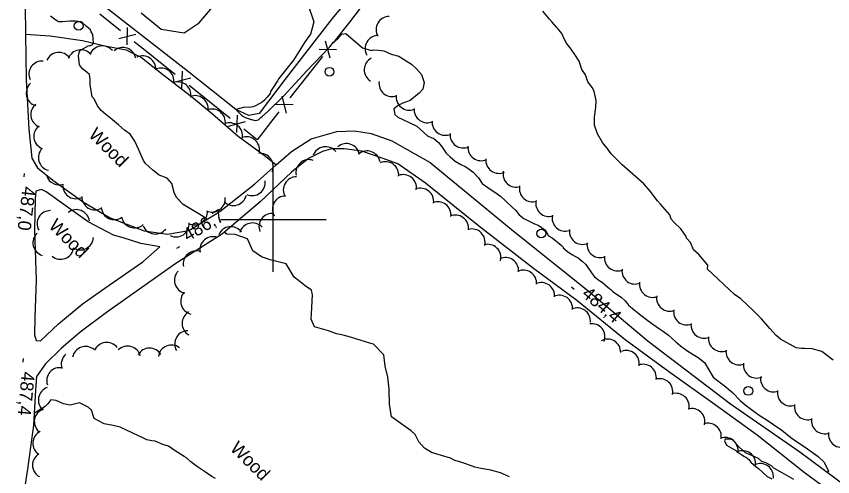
# Model space of a CAD drawing. Extents: x 642515 to 647219, y 6080136 to 6084356.
# Drawn here: x 642941.6 to 643127.5, y 6082341.5 to 6082446.4 of the extents above; entities that cross this region are included whole.
import ezdxf

# ---------------------------------------------------------------- set-up
doc = ezdxf.new("R2010")
doc.units = 0
for name, color, linetype in [('Level 19', 7, 'Continuous'), ('Level 2', 7, 'Continuous'), ('Level 21', 7, 'Continuous'), ('Level 22', 7, 'Continuous'), ('Level 3', 7, 'Continuous'), ('Level 36', 7, 'Continuous'), ('Level 37', 7, 'Continuous'), ('Level 4', 7, 'Continuous'), ('Level 44', 7, 'Continuous'), ('Level 61', 7, 'Continuous')]:
    doc.layers.add(name, color=color, linetype=linetype)

msp = doc.modelspace()

# ---------------------------------------------------------------- linework, layer by layer
at = {"layer": 'Level 19'}
msp.add_lwpolyline([(642969.97, 6082447.17), (642974.56, 6082443.51), (642979.82, 6082442.61), (642983.18, 6082444.95), (642987.04, 6082449.51)], dxfattribs=at)
at = {"layer": 'Level 2'}
for points in [[(643008.19, 6082448.5), (643009.06, 6082445.82), (643009.33, 6082445.11), (643008.96, 6082443.68), (643008.58, 6082442.34), (643007.37, 6082440.67), (643004.71, 6082436.4), (643001.36, 6082432.22), (643001.02, 6082431.68), (642999.93, 6082429.98), (642999.44, 6082429.27), (642999.34, 6082428.82), (642998.7, 6082427.95), (642998.12, 6082427.32), (642997.54, 6082426.85), (642996.2, 6082426.06), (642995.53, 6082425.74), (642994.6, 6082425.65)], [(643115.6, 6082372.84), (643114.66, 6082373.68), (643113.21, 6082375.29), (643111.32, 6082377.44), (643109.53, 6082379.2), (643106.56, 6082382.02), (643105.13, 6082383), (643099.01, 6082388.79), (643099.05, 6082389.68), (643096.98, 6082392.15), (643095.79, 6082393.21), (643095.14, 6082394.87), (643094.2, 6082395.86), (643094.1, 6082396.26), (643092.88, 6082397.97), (643091.43, 6082399.42), (643090.75, 6082400.19), (643090.38, 6082401.13), (643088.31, 6082403.6), (643087.62, 6082404.37), (643085.9, 6082406.53), (643084.51, 6082408.23), (643079.52, 6082412.56), (643078.24, 6082413.86), (643077.04, 6082415.09), (643076.35, 6082416.02), (643075.05, 6082417.64), (643073.9, 6082419.6), (643073.23, 6082421.57), (643073.22, 6082423.42), (643073.52, 6082425.61), (643073.6, 6082427.22), (643073.29, 6082428.57), (643073.18, 6082429.29), (643072.81, 6082430.07), (643071.77, 6082431.47), (643071.49, 6082432.18), (643071.21, 6082433.05), (643070.33, 6082434.29), (643069.75, 6082436.19), (643068.79, 6082437.67), (643067.91, 6082438.92), (643066.87, 6082440.31), (643066.34, 6082441.25), (643065.79, 6082442.51), (643064.84, 6082443.67), (643064.58, 6082443.9), (643063.64, 6082445.05), (643063.03, 6082445.75), (643061.48, 6082447.6)], [(642977.53, 6082406.23), (642976.94, 6082408.28), (642975.91, 6082409.51), (642974.09, 6082410.22), (642972.66, 6082411.35), (642970.97, 6082412.87), (642970.53, 6082413.57), (642969.35, 6082416.15), (642968.53, 6082417.96), (642967.48, 6082419.51), (642966.22, 6082420.48), (642964.86, 6082421.7), (642963.43, 6082422.83), (642961.91, 6082424.04), (642960.9, 6082424.95), (642960.03, 6082426.03), (642959.31, 6082427.59), (642958.8, 6082428.05), (642958.41, 6082430.83), (642958.35, 6082432.11), (642958.22, 6082433.15), (642957.71, 6082433.61), (642956.61, 6082434.43), (642955.92, 6082435.36), (642955.74, 6082437.36), (642955.93, 6082438.41), (642956.16, 6082438.66), (642958.04, 6082439.72), (642958.29, 6082439.65), (642958.92, 6082440), (642959.15, 6082440.25), (642958.97, 6082442.25), (642958.61, 6082442.87), (642958.43, 6082443.35), (642957.92, 6082443.8), (642957.49, 6082444.18), (642956.65, 6082444.94), (642956.23, 6082445.16), (642955.09, 6082445.26), (642953.72, 6082445.27), (642952.03, 6082445.11), (642951.14, 6082445.14), (642950.55, 6082445.52), (642949.37, 6082446.42)], [(642994.6, 6082425.65), (642993.47, 6082425.68), (642992.99, 6082425.57), (642991.55, 6082425.18), (642992.83, 6082423.88), (642993.29, 6082423.54), (642993.91, 6082423.29), (642995.02, 6082422.9), (642995.15, 6082422.87), (642995.97, 6082422.67), (642996.69, 6082422.79), (642997.23, 6082423.37), (642997.62, 6082423.63), (642998.94, 6082424.75), (643002.41, 6082428.21), (643007.75, 6082433.98), (643012.98, 6082439.46), (643013.78, 6082440.51), (643014.94, 6082441.53), (643015.71, 6082442.37), (643016.59, 6082442.5), (643020.4, 6082439.24), (643022.46, 6082438.62), (643022.93, 6082438.8), (643024.07, 6082438.7), (643025.29, 6082438.52), (643026.95, 6082437.8), (643028.67, 6082437.32), (643029.76, 6082436.65), (643031.6, 6082435.46), (643032.7, 6082434.47), (643033.82, 6082433.16), (643034.48, 6082431.35), (643034.15, 6082429.81), (643033.31, 6082428.88), (643031.29, 6082427.18), (643030.01, 6082426.79), (643028.74, 6082426.24), (643027.58, 6082425.3), (643027.8, 6082424.03), (643028.48, 6082423.42), (643031.05, 6082422.19), (643032.75, 6082421.35), (643034.28, 6082419.98), (643035.21, 6082419.14), (643036.2, 6082418.71), (643036.61, 6082418.65), (643037.71, 6082417.66), (643038.58, 6082416.58), (643039.46, 6082415.18)], [(643039.46, 6082415.18), (643040.39, 6082414.35), (643041.49, 6082413.36), (643042.82, 6082412.62), (643043.81, 6082412.19), (643044.4, 6082411.82), (643045.58, 6082410.92), (643046.86, 6082409.62), (643047.65, 6082408.29), (643048.99, 6082407.4), (643051.09, 6082405.98), (643051.84, 6082405.45), (643054.31, 6082403.09), (643055.32, 6082402.18), (643056.1, 6082401.18), (643057.19, 6082400.35), (643058.19, 6082399.76), (643059.6, 6082399.1), (643060.43, 6082398.83), (643061.93, 6082397.78), (643062.37, 6082397.08), (643062.81, 6082396.38), (643063.64, 6082395.94), (643065.63, 6082394.23), (643066.1, 6082393.82), (643066.15, 6082393.62), (643067.08, 6082392.78), (643068.08, 6082392.11), (643069.04, 6082391.56), (643069.5, 6082391.38), (643070.42, 6082390.62), (643071.31, 6082389.83), (643072.54, 6082387.96), (643073.27, 6082387), (643074.24, 6082386.28), (643075.04, 6082385.72), (643076.3, 6082384.66), (643077.02, 6082384.1), (643077.53, 6082383.64), (643079.41, 6082382.33), (643080.26, 6082381.57), (643080.52, 6082381.19), (643080.99, 6082380.61), (643082.26, 6082379.55), (643083.82, 6082378.31), (643085.42, 6082377.1), (643086.55, 6082376.24), (643088.02, 6082375.15), (643088.98, 6082374.6), (643090.11, 6082373.73), (643091.76, 6082372.25), (643092.86, 6082371.34)], [(642984.97, 6082400.14), (642984.11, 6082400.79), (642979.53, 6082403.52), (642978.07, 6082405.13), (642977.53, 6082406.23)], [(643053.9, 6082341.46), (643051.84, 6082342.39), (643049.62, 6082343), (643047.35, 6082343.36), (643045.96, 6082343.69), (643043.98, 6082344.4), (643042.59, 6082344.89), (643041.44, 6082345.15), (643040.44, 6082345.74), (643038.39, 6082346.35), (643036.1, 6082347.04), (643034.51, 6082348), (643033.23, 6082349.45), (643032.42, 6082351.09), (643031.49, 6082351.93), (643028.06, 6082354.4), (643027.05, 6082355.15), (643026.58, 6082358), (643026.49, 6082361.44), (643026.19, 6082364.15), (643025.58, 6082366.68), (643025.29, 6082369.23), (643022.91, 6082371.67), (643022.09, 6082371.95), (643020.12, 6082372.49), (643017.66, 6082373.32), (643016.02, 6082373.72), (643014.47, 6082374.04), (643012.65, 6082374.75), (643009.46, 6082375.63), (643008.73, 6082377.36), (643008.82, 6082378.64), (643009.01, 6082382.9), (643008.8, 6082384.01), (643007.37, 6082384.98), (643005.86, 6082386.18), (643004.85, 6082386.93), (643003, 6082389.96), (643001.53, 6082390.37), (642999.4, 6082390.9), (642997.42, 6082391.61), (642995.42, 6082392.95), (642994.23, 6082395.69), (642991.43, 6082396.67), (642989.49, 6082396.73), (642988.88, 6082397.19)], [(643092.86, 6082371.34), (643094.29, 6082370.21), (643095.75, 6082369.36), (643096.88, 6082368.66), (643098.31, 6082367.53), (643100.25, 6082364.18), (643101.93, 6082362.9), (643102.81, 6082362.26), (643104.67, 6082360.68), (643106.42, 6082358.88), (643107.56, 6082357.85), (643108.99, 6082356.8), (643110.75, 6082355.53), (643112.59, 6082354.34), (643114.05, 6082353.41), (643115.93, 6082352.11), (643117.95, 6082350.44), (643119.5, 6082349.36), (643121.22, 6082348.2), (643123.14, 6082346.86), (643124.19, 6082346.07), (643125.5, 6082344.9), (643126.58, 6082342.79), (643126.36, 6082342.44)], [(643127.58, 6082368.06), (643125.05, 6082370.02), (643122.83, 6082370.64), (643121.05, 6082370.71), (643120.4, 6082370.67), (643119.18, 6082370.85), (643115.6, 6082372.84)], [(642986.92, 6082341.11), (642986.09, 6082341.55), (642984.67, 6082342.52), (642982.84, 6082343.71), (642981.32, 6082344.91), (642980.31, 6082345.82), (642979.81, 6082346.11), (642977.73, 6082347.36), (642976.23, 6082348.41), (642974.92, 6082348.82), (642973.18, 6082349.61), (642972.45, 6082349.65), (642971.31, 6082349.92), (642970.65, 6082350.2), (642965.2, 6082352.8), (642963.65, 6082353.13), (642961.53, 6082353.5), (642959.29, 6082354.74), (642958.71, 6082356.63), (642957.95, 6082357.31), (642955.96, 6082358.33), (642953.81, 6082357.82), (642952.34, 6082358.07), (642950.61, 6082358.86), (642949.39, 6082359.04), (642948.71, 6082358.13), (642948.1, 6082357.46), (642946.5, 6082356.46), (642945.61, 6082355.87)], [(643118.67, 6082340.86), (643117.62, 6082341.49), (643115.96, 6082342.37), (643114.13, 6082343.4), (643113.54, 6082343.93), (643112.25, 6082344.63), (643111.35, 6082344.98), (643110.63, 6082345.63), (643108.69, 6082346.45), (643107.65, 6082346.92), (643106.09, 6082348.32), (643105.31, 6082349.25), (643104.68, 6082349.89), (643103.86, 6082350.01), (643103.01, 6082350.01), (643102.83, 6082349.64), (643103.28, 6082348.7), (643105.44, 6082347.45), (643105.7, 6082347.22), (643106.37, 6082346.77), (643106.83, 6082346.44), (643107.45, 6082346.11), (643107.87, 6082345.89), (643108.03, 6082345.74), (643108.37, 6082345.43), (643108.89, 6082344.82), (643109.99, 6082343.83), (643110.58, 6082343.38), (643111.68, 6082342.39), (643112.61, 6082341.56), (643113.61, 6082340.97)]]:
    msp.add_lwpolyline(points, dxfattribs=at)
at = {"layer": 'Level 21'}
for points in [[(642943.54, 6082448.73), (642943.64, 6082442.35), (642943.8, 6082432.02), (642944.4, 6082420.67), (642945.11, 6082414.09), (642946.38, 6082411.9), (642949.87, 6082409.09), (642956.89, 6082404.04), (642962.94, 6082400.47), (642970.65, 6082397.55), (642975.97, 6082396.77), (642980.86, 6082397.58), (642987.9, 6082401.96), (642995.81, 6082408.16), (643000.77, 6082412.55), (643004.22, 6082415.6), (643008.68, 6082418.49), (643014.59, 6082420.16), (643018.56, 6082420.28), (643022.41, 6082419.66), (643027.1, 6082418), (643035.83, 6082413.1), (643045.67, 6082404.99), (643054.75, 6082397.49), (643071.39, 6082384.23), (643085.46, 6082372.34), (643104.25, 6082358.07), (643120, 6082347.12), (643133.04, 6082337.54)], [(643133.69, 6082333.12), (643121.04, 6082342.44), (643110.29, 6082350.98), (643100.73, 6082357.84), (643090.41, 6082365.23), (643080.24, 6082372.71), (643069.22, 6082381.64), (643059.39, 6082388.9), (643046.81, 6082398.69), (643034.76, 6082408.38), (643028.45, 6082412.8), (643024.92, 6082414.11), (643020.28, 6082415.66), (643016.23, 6082416.23), (643013.35, 6082416.2), (643011.27, 6082415.61), (643008.11, 6082413.99), (643004.24, 6082410.89), (642997.08, 6082404.16), (642988.5, 6082396.87), (642977.88, 6082390.05), (642970.18, 6082384.59), (642962.09, 6082378.87), (642956.11, 6082374.46), (642951.8, 6082370.7), (642948.2, 6082367.22), (642946.19, 6082364.3), (642945.89, 6082361.23), (642945.47, 6082353.24), (642944.11, 6082343.18), (642942.74, 6082334.48)], [(642963.69, 6082396.54), (642957.92, 6082399.56), (642952.93, 6082403.1), (642948.35, 6082406.42), (642947.27, 6082406.93), (642945.99, 6082406.54), (642945.85, 6082404.84), (642945.71, 6082397.66), (642946.06, 6082386.24), (642945.75, 6082377.84), (642945.67, 6082373.81), (642946.07, 6082372.54), (642947.04, 6082372.43), (642951.19, 6082376.34), (642956.59, 6082380.8), (642961.72, 6082384.44), (642970.36, 6082390.43), (642974.21, 6082393.85), (642969.95, 6082394.6), (642965.9, 6082395.93), (642963.69, 6082396.54)]]:
    msp.add_lwpolyline(points, dxfattribs=at)
at = {"layer": 'Level 22'}
msp.add_lwpolyline([(642943.64, 6082442.35), (642949.28, 6082441.96), (642956.65, 6082440.92), (642961.69, 6082439.69), (642966.55, 6082438.77), (642970.08, 6082436.99), (642975.26, 6082432.95), (642981.49, 6082428.13), (642986.3, 6082424.12), (642992.06, 6082419.12), (642998.29, 6082414.52), (642999.93, 6082413.24), (643000.77, 6082412.55)], dxfattribs=at)
at = {"layer": 'Level 3'}
for p, q in [((642943.35, 6082410.59), (642943.26, 6082409.8)), ((642978.1, 6082393.56), (642978.79, 6082393.97)), ((643067.98, 6082384.72), (643068.59, 6082384.19)), ((642943.11, 6082368.4), (642943.03, 6082367.61))]:
    msp.add_line(p, q, dxfattribs=at)
at = {"layer": 'Level 36'}
for centre in [(642955.75, 6082444.23), (643012.87, 6082433.77), (643061.14, 6082396.9), (643108.3, 6082361.04)]:
    msp.add_circle(centre, 1, dxfattribs=at)
at = {"layer": 'Level 37'}
for p, q in [((643021.1, 6082449.86), (643017.45, 6082445.1)), ((642965.27, 6082443.12), (642960.58, 6082446.86)), ((642966.78, 6082439.87), (642966.9, 6082443.87)), ((642964.9, 6082441.37), (642968.77, 6082442.37)), ((642973.08, 6082436.87), (642968.39, 6082440.62)), ((643013.02, 6082436.88), (643012, 6082440.75)), ((643014.51, 6082438.76), (643010.51, 6082438.86)), ((643011.27, 6082437.24), (643007.56, 6082432.53)), ((642977.4, 6082431.38), (642981.28, 6082432.39)), ((642979.28, 6082429.88), (642979.4, 6082433.88)), ((643007.56, 6082432.53), (643003.84, 6082427.82)), ((642985.59, 6082426.89), (642980.9, 6082430.64)), ((642990.28, 6082423.15), (642985.59, 6082426.89)), ((643003.12, 6082424.32), (643002.09, 6082428.18)), ((643004.6, 6082426.2), (643000.6, 6082426.3)), ((642991.79, 6082419.91), (642991.91, 6082423.91)), ((642989.91, 6082421.4), (642993.78, 6082422.41))]:
    msp.add_line(p, q, dxfattribs=at)
for points in [[(643017.45, 6082445.1), (643016.23, 6082443.52), (643013.75, 6082440.38)], [(642977.77, 6082433.13), (642973.27, 6082436.72), (642973.08, 6082436.87)], [(643001.36, 6082424.67), (642999.42, 6082422.21), (642997.71, 6082419.92)], [(642997.71, 6082419.92), (642996.45, 6082418.23), (642993.41, 6082420.66)]]:
    msp.add_lwpolyline(points, dxfattribs=at)
at = {"layer": 'Level 4'}
msp.add_lwpolyline([(643113.71, 6082572.15), (643110.35, 6082567.9), (643106.4, 6082562.65), (643102.21, 6082557.18), (643101.07, 6082555.7), (643096.48, 6082550.09), (643091.7, 6082543.74), (643081.64, 6082531.03), (643068.04, 6082514.73), (643056.8, 6082500.35), (643042.98, 6082482.6), (643027.74, 6082463.11), (643013.51, 6082445.94), (643003, 6082432.38), (642996.89, 6082424.23), (642994.48, 6082423.79), (642991.55, 6082425.18), (642980.46, 6082434.01), (642959.86, 6082449.97), (642950.95, 6082457.15), (642947.85, 6082460.08)], dxfattribs=at)
at = {"layer": 'Level 44'}
for centre, start, end in [((643026.51, 6082443.36), 90.0099, 209.9878), ((643024.01, 6082439.03), 90.0099, 209.9878), ((642951.24, 6082435.17), 35.1387, 155.1166), ((642956.23, 6082435.76), 40.2032, 160.1811), ((642961.15, 6082436.65), 40.2032, 160.1811), ((642965.82, 6082436.28), 11.229, 131.207), ((642947.41, 6082433.21), 84.3476, 204.3256), ((642970.33, 6082434.38), 356.6152, 116.5931), ((643023.81, 6082434.19), 117.7182, 237.6961), ((642974.46, 6082431.62), 350.8945, 110.8725), ((642946.81, 6082428.92), 132.2453, 252.2232), ((642978.34, 6082428.46), 350.8945, 110.8725), ((643027.16, 6082431.12), 171.5788, 291.5567), ((642982.25, 6082425.33), 351.9821, 111.96), ((643031.08, 6082428.01), 171.5788, 291.5567), ((642947.86, 6082424.01), 127.8799, 247.8578), ((642986.18, 6082422.25), 351.9821, 111.96), ((643035.16, 6082425.15), 174.99, 294.968), ((642948.54, 6082419.06), 127.8799, 247.8578), ((642990.09, 6082419.14), 350.5424, 110.5204), ((643039.25, 6082422.28), 174.99, 294.968), ((643043.35, 6082419.4), 174.5846, 294.5626), ((642993.95, 6082415.96), 350.5424, 110.5204), ((642949.59, 6082414.22), 136.1657, 256.1436), ((643011.98, 6082413.67), 39.4306, 159.4085), ((643016.75, 6082414.4), 10.4066, 130.3845), ((643021.46, 6082412.72), 10.4066, 130.3845), ((643047.42, 6082416.5), 174.5846, 294.5626), ((642997.07, 6082412.19), 335.8103, 95.7883), ((643051.49, 6082413.61), 174.5846, 294.5626), ((643008.21, 6082410.74), 70.6124, 190.5903), ((643025.66, 6082410.26), 354.1805, 114.1585), ((643029.7, 6082407.33), 351.6539, 111.6318), ((643055.42, 6082410.47), 168.1295, 288.1074), ((642951.34, 6082410.96), 198.2009, 288.6883), ((642995.26, 6082408.54), 247.0396, 7.0176), ((643005.37, 6082406.83), 90.2765, 210.2544), ((642955.15, 6082407.83), 179.4637, 299.4417), ((643033.62, 6082404.23), 351.6539, 111.6318), ((643059.14, 6082407.13), 168.1295, 288.1074), ((642959.46, 6082405.29), 179.4637, 299.4417), ((642986.15, 6082404.8), 245.481, 5.4589), ((642991.01, 6082406.29), 225.9667, 345.9447), ((643002.89, 6082402.48), 90.2765, 210.2544), ((642963.9, 6082403.06), 184.7017, 304.6796), ((643037.57, 6082401.15), 352.7589, 112.7369), ((643062.87, 6082403.79), 168.1295, 288.1074), ((642949.28, 6082399.12), 88.9361, 208.914), ((642955.23, 6082399.35), 8.0072, 127.9852), ((642982.08, 6082401.9), 243.8922, 3.8701), ((642999.82, 6082398.48), 82.2791, 202.257), ((643041.55, 6082398.12), 352.7589, 112.7369), ((643066.59, 6082400.45), 168.1295, 288.1074), ((642968.49, 6082401.19), 191.1889, 311.1669), ((642977.93, 6082399.12), 243.8922, 3.8701), ((642995.37, 6082396.31), 43.8048, 163.7828), ((642973.22, 6082399.79), 201.7282, 321.7061), ((642990.41, 6082395.46), 36.869, 156.847), ((643045.34, 6082394.94), 345.7287, 105.7066), ((643070.53, 6082397.43), 172.9135, 292.8915), ((642948.34, 6082394.8), 132.9924, 252.9704), ((642956.11, 6082396.16), 236.7014, 356.6794), ((642986.37, 6082393.19), 70.4418, 190.4197), ((642951.62, 6082394.03), 230.6803, 350.6582), ((643048.92, 6082391.45), 345.7287, 105.7066), ((643074.52, 6082394.41), 172.9135, 292.8915), ((642982.57, 6082389.94), 70.4418, 190.4197), ((643078.51, 6082391.39), 172.9135, 292.8915), ((643052.96, 6082388.43), 355.3008, 115.2787), ((642980.57, 6082386.26), 136.534, 256.5119), ((643057.07, 6082385.58), 355.3008, 115.2787), ((643082.5, 6082388.38), 172.9135, 292.8915), ((643061.17, 6082382.72), 354.9434, 114.9213), ((643086.49, 6082385.35), 171.086, 291.064), ((642981.99, 6082381.47), 136.534, 256.5119), ((643065.26, 6082379.85), 354.6657, 114.6437), ((643090.38, 6082382.21), 171.086, 291.064), ((642982.31, 6082376.43), 120.1215, 240.0995), ((643069.33, 6082376.96), 354.6657, 114.6437), ((643094.27, 6082379.07), 171.086, 291.064), ((643072.64, 6082373.36), 339.1228, 99.1008), ((643098.23, 6082376.03), 172.8286, 292.8065), ((642980.63, 6082371.72), 89.7504, 209.7283), ((643102.21, 6082373.01), 172.8286, 292.8065), ((642957.32, 6082368.18), 49.572, 169.5499), ((642962.15, 6082369.08), 37.593, 157.5709), ((642966.9, 6082368.25), 15.1156, 135.0935), ((642976.9, 6082368.5), 52.8616, 172.8396), ((643076.23, 6082369.83), 359.4937, 119.4717), ((642954.78, 6082367.09), 129.7857, 198.5485), ((642971.91, 6082367.79), 30.8208, 150.7987), ((643080.46, 6082367.25), 350.85, 110.8279), ((643106.19, 6082369.98), 172.8286, 292.8065), ((643110.17, 6082366.96), 172.8286, 292.8065), ((642951.47, 6082363.34), 78.5705, 198.5484), ((643084.34, 6082364.1), 350.85, 110.8279), ((643088.1, 6082360.83), 348.1348, 108.1127), ((643114.06, 6082363.8), 170.6222, 290.6001), ((642949.58, 6082358.96), 109.3474, 229.3253), ((643091.83, 6082357.49), 348.1348, 108.1127), ((643117.92, 6082360.62), 170.6222, 290.6001), ((642948.65, 6082354.05), 109.3474, 229.3253), ((643095.41, 6082354.02), 345.8267, 105.8046), ((643121.79, 6082357.45), 170.6222, 290.6001), ((643125.65, 6082354.28), 170.6222, 290.6001), ((643099.14, 6082350.66), 349.8813, 109.8592), ((642948.32, 6082349.1), 117.1589, 237.1369), ((643129.55, 6082351.15), 171.5716, 291.5496), ((643102.96, 6082347.44), 349.8813, 109.8592), ((643106.96, 6082344.41), 354.249, 114.227), ((642948.24, 6082344.13), 121.2984, 241.2764), ((643111.02, 6082341.48), 354.249, 114.227)]:
    msp.add_arc(centre, 3, start, end, dxfattribs=at)
at = {"layer": 'Level 61'}
for p, q in [((643000, 6082412.16), (643000, 6082388.16)), ((643012.16, 6082400), (642988.16, 6082400))]:
    msp.add_line(p, q, dxfattribs=at)

# ---------------------------------------------------------------- texts
at = {"layer": 'Level 3'}
for s, rotation, p in [('487,0', 263.3723, (642942.99, 6082407.74)), ('486,7', 30.3291, (642980.61, 6082394.98)), ('484,4', 319.2445, (643070.14, 6082382.81)), ('487,4', 264.5924, (642942.8, 6082365.54))]:
    msp.add_text(s, height=3, rotation=rotation, dxfattribs=at).set_placement(p)
at = {"layer": 'Level 44'}
for p in [(642957.81, 6082419.2), (642948.72, 6082398.44), (642990.06, 6082347.73)]:
    msp.add_text('Wood', height=3, rotation=315.1749, dxfattribs=at).set_placement(p)

doc.saveas('drawing.dxf')
